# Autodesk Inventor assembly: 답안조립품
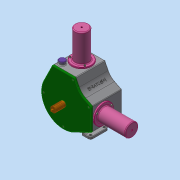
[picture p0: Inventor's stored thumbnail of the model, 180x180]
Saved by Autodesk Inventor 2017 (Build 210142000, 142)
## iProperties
Part Number: 답안조립품
Material: 일반
Document SubType Name: Assembly
Designer: MRC
Mass: 3748.67 g
Surface Area: 4101.75 cm^2
Volume: 1119.43 cm^3
Density: 3.34872 g/cm^3
Author: MRC
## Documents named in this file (13)
- C:\Users\MRC\Desktop\611109V1009\답안조립품.iam
- C:\Users\MRC\Desktop\611109V1009\본체.ipt
- C:\Users\MRC\Desktop\611109V1009\너트 M3.ipt
- C:\Users\MRC\Desktop\611109V1009\베어링 20 x 37 x 9.ipt
- C:\Users\MRC\Desktop\611109V1009\볼트 M3 x 12.ipt
- C:\Users\MRC\Desktop\611109V1009\실린더.ipt
- C:\Users\MRC\Desktop\611109V1009\앞커버.ipt
- C:\Users\MRC\Desktop\611109V1009\축.ipt
- C:\Users\MRC\Desktop\611109V1009\측정게이지.ipt
- C:\Users\MRC\Desktop\611109V1009\커넥팅로드 캡.ipt
- C:\Users\MRC\Desktop\611109V1009\커넥팅로드.ipt
- C:\Users\MRC\Desktop\611109V1009\피스톤 핀.ipt
- C:\Users\MRC\Desktop\611109V1009\피스톤.ipt
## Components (4 placed, 2 different names)
1. 피스톤 핀:1 — 플러쉬:3
2. 피스톤:1 — 플러쉬:1, 플러쉬:4
3. 피스톤:2 — 플러쉬:2, 플러쉬:3
4. 피스톤 핀:2 — 플러쉬:4
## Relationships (4: Flush 4)
- 플러쉬:1 [Flush]: 피스톤:1
- 플러쉬:2 [Flush]: 피스톤:2
- 플러쉬:3 [Flush]: 피스톤 핀:1 ↔ 피스톤:2
- 플러쉬:4 [Flush]: 피스톤:1 ↔ 피스톤 핀:2
